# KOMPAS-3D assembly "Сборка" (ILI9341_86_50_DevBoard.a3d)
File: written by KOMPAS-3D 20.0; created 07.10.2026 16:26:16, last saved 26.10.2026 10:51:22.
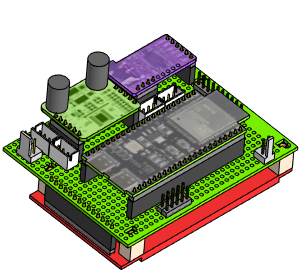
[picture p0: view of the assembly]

Document properties: Полное имя файла: D:\RicWork\Project-EPS32\box_compas\сборки компонентов\ILI9341_86_50_DevBoard.a3d

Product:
- Part/product: Сборка
    Масса: 0.245268
  - Component [assembly]: Сборка  | Масса: 0.11309; source file: ..\монитор\ILI9341_86_50 asm+.a3d
  - Component [assembly]: Сборка  | Масса: 0.132179; source file: макетка+модули.a3d

Referenced files in D:\RicWork\Project-EPS32\box_compas\монитор\: ILI9341_86_50 asm+.a3d
Referenced files in D:\RicWork\Project-EPS32\box_compas\сборки компонентов\: макетка+модули.a3d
